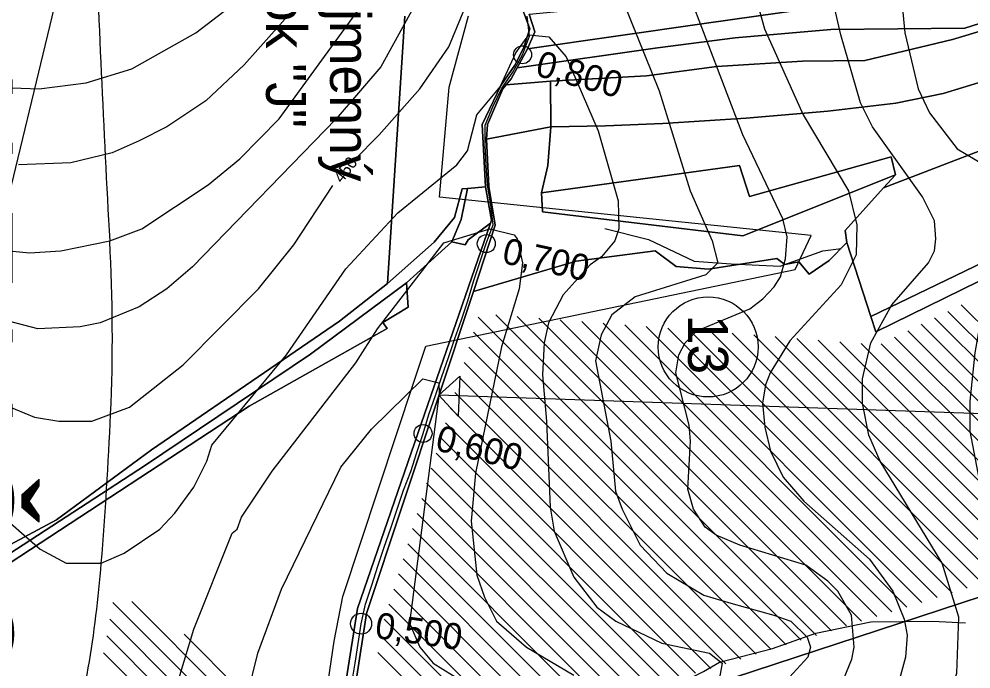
# Model space of a CAD drawing. Extents: x -510989 to -501240, y -1184665 to -1176089.
# Drawn here: x -509320.3 to -508844.5, y -1178920.9 to -1178596.2 of the extents above; entities that cross this region are included whole.
import ezdxf

# ---------------------------------------------------------------- set-up
doc = ezdxf.new("R2010")
doc.units = 0
for name, color, linetype in [('lesni_pozemek', 7, 'Continuous'), ('NAVRH_rozvodnice', 7, 'Continuous'), ('orna_puda', 7, 'Continuous'), ('ostatni_plocha_x_neplodna_puda', 7, 'Continuous'), ('ostatni_plocha_x_ostatni_komunikace', 7, 'Continuous'), ('popis', 7, 'Continuous'), ('STAV_erozne_ohrozene_plochy', 7, 'Continuous'), ('STAV_odtokove_linie', 7, 'Continuous'), ('STAV_systematicke_odvodneni', 7, 'Continuous'), ('STAV_vyrazne_udolnice', 7, 'Continuous'), ('trasovani_toku', 7, 'Continuous'), ('trvaly_travni_porost', 7, 'Continuous'), ('vodni_plocha_x_vodni_tok_v_koryt_prir_n_upr', 7, 'Continuous'), ('vrstevnice_01', 7, 'Continuous'), ('vrstevnice_02', 7, 'Continuous'), ('vrstevnice_04', 7, 'Continuous')]:
    doc.layers.add(name, color=color, linetype=linetype)

msp = doc.modelspace()

# ---------------------------------------------------------------- linework, layer by layer
at = {"layer": 'lesni_pozemek'}
for points in [[(-508694.2, -1178531.12), (-508773.17, -1178567.76), (-508848.8, -1178589.27), (-508905.8, -1178590.26), (-508927.09, -1178591.28), (-508977.94, -1178598.38), (-509066.11, -1178611.08), (-509062.51, -1178602.52), (-509065.29, -1178593.71), (-509035.54, -1178590.95), (-509002.31, -1178585.02), (-508917.7, -1178573.41), (-508856.26, -1178566.38), (-508819.35, -1178554.28), (-508781.68, -1178540.86), (-508765.23, -1178532.27), (-508699.99, -1178506.32)], [(-508691.9, -1178539.27), (-508717.79, -1178553.24), (-508749.42, -1178566.28), (-508768.45, -1178575.36), (-508847.66, -1178600.8), (-508914.58, -1178601.44), (-508962.38, -1178605.49), (-509001.19, -1178610.54), (-509071.33, -1178620.51), (-509066.11, -1178611.08), (-508977.94, -1178598.38), (-508927.09, -1178591.28), (-508905.8, -1178590.26), (-508848.8, -1178589.27), (-508773.17, -1178567.76), (-508694.2, -1178531.12)], [(-508689.7, -1178547.08), (-508768.8, -1178580.92), (-508819.34, -1178596.04), (-508853.82, -1178606.35), (-508897.56, -1178616.84), (-508928.77, -1178617.24), (-508971.61, -1178619.89), (-509006.67, -1178624.56), (-509054.7, -1178627.16), (-509076.91, -1178629.11), (-509074.36, -1178626), (-509071.33, -1178620.51), (-509001.19, -1178610.54), (-508962.38, -1178605.49), (-508914.58, -1178601.44), (-508847.66, -1178600.8), (-508768.45, -1178575.36), (-508749.42, -1178566.28), (-508717.79, -1178553.24), (-508691.9, -1178539.27)], [(-508685.06, -1178563.52), (-508683.92, -1178574.65), (-508712.94, -1178585.61), (-508741.33, -1178597.92), (-508796.54, -1178617.89), (-508838.72, -1178627.31), (-508858.45, -1178633.41), (-508882.13, -1178638.15), (-508916.08, -1178642.26), (-508956.82, -1178645.68), (-508998.59, -1178648.35), (-509027.25, -1178649.57), (-509054.58, -1178650.03), (-509054.7, -1178627.16), (-509006.67, -1178624.56), (-508971.61, -1178619.89), (-508928.77, -1178617.24), (-508897.56, -1178616.84), (-508853.82, -1178606.35), (-508819.34, -1178596.04), (-508768.8, -1178580.92), (-508689.7, -1178547.08)], [(-508712.94, -1178585.61), (-508683.92, -1178574.65), (-508680.85, -1178604.64), (-508791.99, -1178643.51), (-508888.15, -1178680.51), (-508882.24, -1178674), (-508884.37, -1178665.06), (-508955.25, -1178684.75), (-508960.15, -1178669.29), (-509059.22, -1178683.03), (-509056.08, -1178669.28), (-509054.58, -1178650.03), (-509027.25, -1178649.57), (-508998.59, -1178648.35), (-508956.82, -1178645.68), (-508916.08, -1178642.26), (-508882.13, -1178638.15), (-508858.45, -1178633.41), (-508838.72, -1178627.31), (-508796.54, -1178617.89), (-508741.33, -1178597.92)], [(-508680.85, -1178604.64), (-508669.27, -1178651.7), (-508749.47, -1178676.41), (-508794.13, -1178696.5), (-508842.69, -1178719.84), (-508894.51, -1178744.76), (-508906.64, -1178707.76), (-508907.44, -1178701.76), (-508888.15, -1178680.51), (-508791.99, -1178643.51)]]:
    msp.add_lwpolyline(points, close=True, dxfattribs=at)
at = {"layer": 'NAVRH_rozvodnice'}
for centre, radius, start, end in [((-501370.86, -1178265.59), 7916.45, 181.979217, 183.19639), ((-510129.72, -1178754.73), 856.05, 357.40438, 3.19639), ((-511480, -1178693.52), 2207.72, 355.46708, 357.40438), ((-509866.59, -1178821.43), 589.24, 345.19507, 355.46708)]:
    msp.add_arc(centre, radius, start, end, dxfattribs=at)
at = {"layer": 'orna_puda'}
for points in [[(-509070.81, -1178585.19), (-509064.96, -1178601), (-509068.2, -1178610.67), (-509072.47, -1178619.27), (-509079.57, -1178629.42), (-509088.82, -1178648.83), (-509087.14, -1178679.95), (-509096.12, -1178680.81), (-509098.79, -1178681.07), (-509102.66, -1178695.24), (-509112.8, -1178707.68), (-509136.21, -1178728.22), (-509127.44, -1178594.74)], [(-509324.76, -1178867.81), (-509205.31, -1178789.52), (-509136.23, -1178750.79), (-509138.56, -1178747.71), (-509125.79, -1178740.08), (-509126.72, -1178727.98), (-509104.07, -1178707.47), (-509097.3, -1178708.89), (-509095.81, -1178706.46), (-509084.62, -1178698.12), (-509117.59, -1178793.61), (-509151.09, -1178890.59), (-509168.68, -1179001.25), (-509186.91, -1179112.93)], [(-508838.84, -1178884.57), (-508994.39, -1178935.46), (-509162.19, -1178993.59), (-509146.65, -1178893.13), (-509093.21, -1178732.21), (-509041.89, -1178717.09), (-509002.41, -1178711.97), (-508991.88, -1178719.79), (-508975.78, -1178721.18), (-508941.58, -1178715.83), (-508937.49, -1178718.86), (-508930.53, -1178717.43), (-508925.43, -1178723.64), (-508915.45, -1178716.88), (-508906.64, -1178707.76), (-508894.51, -1178744.76), (-508892.02, -1178752.36), (-508779.86, -1178697.4)]]:
    msp.add_lwpolyline(points, dxfattribs=at)
at = {"layer": 'ostatni_plocha_x_neplodna_puda'}
for points in [[(-508667.58, -1178658.57), (-508779.86, -1178697.4), (-508892.02, -1178752.36), (-508894.51, -1178744.76), (-508842.69, -1178719.84), (-508794.13, -1178696.5), (-508749.47, -1178676.41), (-508669.27, -1178651.7)], [(-509098.79, -1178681.07), (-509096.12, -1178680.81), (-509099.38, -1178696.28), (-509104.07, -1178707.47), (-509126.72, -1178727.98), (-509174.65, -1178763.65), (-509257.53, -1178819.36), (-509328.77, -1178865.74), (-509341.07, -1178870.59), (-509343.66, -1178866.41), (-509331.92, -1178862.59), (-509301.57, -1178846.31), (-509254.05, -1178811.34), (-509160.2, -1178747.16), (-509136.21, -1178728.22), (-509112.8, -1178707.68), (-509102.66, -1178695.24)], [(-509096.12, -1178680.81), (-509087.14, -1178679.95), (-509084.09, -1178696.58), (-509084.62, -1178698.12), (-509095.81, -1178706.46), (-509097.3, -1178708.89), (-509104.07, -1178707.47), (-509099.38, -1178696.28)]]:
    msp.add_lwpolyline(points, close=True, dxfattribs=at)
at = {"layer": 'ostatni_plocha_x_ostatni_komunikace'}
msp.add_lwpolyline([(-509126.72, -1178727.98), (-509125.79, -1178740.08), (-509138.56, -1178747.71), (-509136.23, -1178750.79), (-509205.31, -1178789.52), (-509324.76, -1178867.81), (-509358.82, -1178882.2), (-509377.09, -1178891.95), (-509408.27, -1178926.19), (-509410.12, -1178922.08), (-509408.07, -1178919.73), (-509378.4, -1178889.53), (-509357.59, -1178878.19), (-509341.07, -1178870.59), (-509328.77, -1178865.74), (-509257.53, -1178819.36), (-509174.65, -1178763.65)], close=True, dxfattribs=at)
at = {"layer": 'STAV_erozne_ohrozene_plochy'}
for p, q in [((-508849.33, -1178738.98), (-508729.27, -1178859.04)), ((-509082, -1178743.9), (-508921.78, -1178904.11)), ((-508856, -1178742.21), (-508737.69, -1178860.51)), ((-509090.76, -1178745.04), (-508929.33, -1178906.47)), ((-509071.26, -1178744.74), (-508914.24, -1178901.76)), ((-509060.52, -1178745.58), (-508906.7, -1178899.4)), ((-509049.78, -1178746.42), (-508899.16, -1178897.04)), ((-509039.03, -1178747.27), (-508891.62, -1178894.68)), ((-509028.29, -1178748.11), (-508884.07, -1178892.33)), ((-508862.66, -1178745.44), (-508746.12, -1178861.99)), ((-509093.11, -1178752.59), (-508936.87, -1178908.83)), ((-509017.55, -1178748.95), (-508876.53, -1178889.97)), ((-509006.81, -1178749.79), (-508868.99, -1178887.61)), ((-508996.07, -1178750.64), (-508861.45, -1178885.25)), ((-508985.32, -1178751.48), (-508853.91, -1178882.89)), ((-508974.58, -1178752.32), (-508846.37, -1178880.54)), ((-508963.84, -1178753.16), (-508838.8, -1178878.2)), ((-508876, -1178751.91), (-508762.97, -1178864.94)), ((-508869.33, -1178748.68), (-508754.55, -1178863.46)), ((-508953.1, -1178754.01), (-508830.38, -1178876.73)), ((-508942.35, -1178754.85), (-508821.95, -1178875.25)), ((-508931.61, -1178755.69), (-508813.52, -1178873.78)), ((-508920.87, -1178756.53), (-508805.1, -1178872.31)), ((-508910.13, -1178757.38), (-508796.67, -1178870.83)), ((-508882.66, -1178755.14), (-508771.4, -1178866.41)), ((-509095.46, -1178760.14), (-508944.41, -1178911.19)), ((-508899.39, -1178758.22), (-508788.25, -1178869.36)), ((-508889.33, -1178758.38), (-508779.82, -1178867.88)), ((-509097.81, -1178767.69), (-508951.95, -1178913.54)), ((-509100.15, -1178775.24), (-508959.49, -1178915.9)), ((-509102.5, -1178782.79), (-508967.03, -1178918.26)), ((-509104.85, -1178790.34), (-508974.58, -1178920.62)), ((-509107.2, -1178797.89), (-508982.12, -1178922.98)), ((-509109.55, -1178805.44), (-508989.66, -1178925.33)), ((-509111.9, -1178812.99), (-508997.2, -1178927.69)), ((-509114.25, -1178820.54), (-509004.74, -1178930.05)), ((-509116.6, -1178828.09), (-509012.29, -1178932.41)), ((-509118.95, -1178835.64), (-509019.83, -1178934.76)), ((-509121.3, -1178843.19), (-509027.37, -1178937.12)), ((-509123.65, -1178850.74), (-509034.91, -1178939.48)), ((-509126, -1178858.29), (-509042.45, -1178941.84)), ((-509128.35, -1178865.84), (-509049.99, -1178944.19)), ((-509130.7, -1178873.39), (-509057.54, -1178946.55)), ((-509133.05, -1178880.94), (-509065.08, -1178948.91)), ((-509273.47, -1178887.61), (-509181.48, -1178979.6)), ((-509263.94, -1178887.24), (-509180.33, -1178970.85)), ((-509135.4, -1178888.49), (-509072.62, -1178951.27)), ((-509274.99, -1178895.99), (-509182.63, -1178988.34)), ((-509137.75, -1178896.04), (-509080.16, -1178953.62)), ((-509276.5, -1178904.38), (-509183.79, -1178997.09)), ((-509237.79, -1178903.49), (-509179.17, -1178962.11)), ((-509139.58, -1178904.11), (-509087.7, -1178955.98)), ((-509278.02, -1178912.76), (-509184.94, -1179005.84)), ((-509140.97, -1178912.62), (-509095.25, -1178958.34))]:
    msp.add_line(p, q, dxfattribs=at)
at = {"layer": 'STAV_odtokove_linie'}
msp.add_line((-508745.75, -1178796.5), (-509110.46, -1178784.16), dxfattribs=at)
msp.add_lwpolyline([(-509100.87, -1178794.55), (-509110.46, -1178784.16), (-509100.07, -1178774.57)], close=True, dxfattribs=at)
msp.add_circle((-508975.86, -1178759.99), 25, dxfattribs=at)
at = {"layer": 'STAV_systematicke_odvodneni'}
for p, q in [((-509274.88, -1178474.44), (-509350.42, -1178787.38)), ((-509105.31, -1178630.27), (-509095.74, -1178594.61)), ((-509110.1, -1178685.09), (-509105.31, -1178630.27)), ((-508924.44, -1178704.25), (-509110.1, -1178685.09)), ((-508932.42, -1178721.28), (-508924.44, -1178704.25)), ((-509117.02, -1178759.6), (-508932.42, -1178721.28)), ((-509122.87, -1178777.16), (-509117.02, -1178759.6)), ((-509158.51, -1178884.67), (-509122.87, -1178777.16)), ((-509162.77, -1178907.02), (-509158.51, -1178884.67)), ((-509169.55, -1178951.83), (-509162.77, -1178907.02))]:
    msp.add_line(p, q, dxfattribs=at)
at = {"layer": 'STAV_vyrazne_udolnice'}
for points in [[(-509027.47, -1178700.74), (-509005.77, -1178706.36), (-508982.86, -1178717.21), (-508964.37, -1178718.41), (-508939.86, -1178719.62), (-508918.56, -1178711.98), (-508909.31, -1178710.78)], [(-509120.31, -1178976.33), (-509071.08, -1178958.75), (-509002.15, -1178934.15), (-508978.24, -1178922.2), (-508970.2, -1178917.47), (-508943.67, -1178910.65), (-508921.97, -1178903.01), (-508894.64, -1178897.39), (-508863.69, -1178896.99), (-508847.22, -1178897.79)]]:
    msp.add_lwpolyline(points, dxfattribs=at)
at = {"layer": 'trasovani_toku'}
for p, q in [((-509065.14, -1178604.66), (-509066.33, -1178594.73)), ((-509068.66, -1178614.02), (-509065.14, -1178604.66)), ((-509073.5, -1178622.77), (-509068.66, -1178614.02)), ((-509079.23, -1178630.97), (-509073.5, -1178622.77)), ((-509083.54, -1178639.99), (-509079.23, -1178630.97)), ((-509087.38, -1178649.22), (-509083.54, -1178639.99)), ((-509087.3, -1178659.22), (-509087.38, -1178649.22)), ((-509086.76, -1178669.21), (-509087.3, -1178659.22)), ((-509086.14, -1178679.19), (-509086.76, -1178669.21)), ((-509084.5, -1178689.05), (-509086.14, -1178679.19)), ((-509083.33, -1178698.98), (-509084.5, -1178689.05)), ((-509086.75, -1178708.38), (-509083.33, -1178698.98)), ((-509089.96, -1178717.85), (-509086.75, -1178708.38)), ((-509093.08, -1178727.35), (-509089.96, -1178717.85)), ((-509095.96, -1178736.93), (-509093.08, -1178727.35)), ((-509099.09, -1178746.43), (-509095.96, -1178736.93)), ((-509102.49, -1178755.83), (-509099.09, -1178746.43)), ((-509105.71, -1178765.3), (-509102.49, -1178755.83)), ((-509108.94, -1178774.76), (-509105.71, -1178765.3)), ((-509112.08, -1178784.26), (-509108.94, -1178774.76)), ((-509115.44, -1178793.67), (-509112.08, -1178784.26)), ((-509118.39, -1178803.23), (-509115.44, -1178793.67)), ((-509121.47, -1178812.74), (-509118.39, -1178803.23)), ((-509124.56, -1178822.25), (-509121.47, -1178812.74)), ((-509128.22, -1178831.56), (-509124.56, -1178822.25)), ((-509131.31, -1178841.07), (-509128.22, -1178831.56)), ((-509134.44, -1178850.57), (-509131.31, -1178841.07)), ((-509137.83, -1178859.97), (-509134.44, -1178850.57)), ((-509140.9, -1178869.49), (-509137.83, -1178859.97)), ((-509144.03, -1178878.99), (-509140.9, -1178869.49)), ((-509147.07, -1178888.52), (-509144.03, -1178878.99)), ((-509149.31, -1178898.26), (-509147.07, -1178888.52)), ((-509150.79, -1178908.15), (-509149.31, -1178898.26)), ((-509152.35, -1178918.03), (-509150.79, -1178908.15)), ((-509153.89, -1178927.91), (-509152.35, -1178918.03))]:
    msp.add_line(p, q, dxfattribs=at)
for centre, radius in [((-509068.66, -1178614.02), 4.5), ((-509086.75, -1178708.38), 4.5), ((-509118.39, -1178803.23), 4.5), ((-509149.31, -1178898.26), 5.25)]:
    msp.add_circle(centre, radius, dxfattribs=at)
at = {"layer": 'trvaly_travni_porost'}
msp.add_lwpolyline([(-509127.44, -1178594.74), (-509136.21, -1178728.22), (-509160.2, -1178747.16), (-509254.05, -1178811.34), (-509301.57, -1178846.31), (-509331.92, -1178862.59)], dxfattribs=at)
for points in [[(-509054.7, -1178627.16), (-509054.58, -1178650.03), (-509086.62, -1178656.21), (-509086.14, -1178648.85), (-509078.48, -1178631.01), (-509076.91, -1178629.11)], [(-509086.62, -1178656.21), (-509054.58, -1178650.03), (-509056.08, -1178669.28), (-509059.22, -1178683.03), (-509058.69, -1178692.51), (-508958.61, -1178704.53), (-508882.24, -1178674), (-508888.15, -1178680.51), (-508907.44, -1178701.76), (-508906.64, -1178707.76), (-508915.45, -1178716.88), (-508925.43, -1178723.64), (-508930.53, -1178717.43), (-508937.49, -1178718.86), (-508941.58, -1178715.83), (-508975.78, -1178721.18), (-508991.88, -1178719.79), (-509002.41, -1178711.97), (-509041.89, -1178717.09), (-509093.21, -1178732.21), (-509082.25, -1178699.18), (-509085.42, -1178679.89)], [(-508882.24, -1178674), (-508958.61, -1178704.53), (-509058.69, -1178692.51), (-509059.22, -1178683.03), (-508960.15, -1178669.29), (-508955.25, -1178684.75), (-508884.37, -1178665.06)], [(-508838.84, -1178884.57), (-508818.38, -1178938.24), (-508862.04, -1178954.97), (-508864.4, -1178955.87), (-508911.92, -1178973.72), (-508920.06, -1178991.6), (-508958.12, -1179018.3), (-508951.95, -1179029.63), (-508984.27, -1179048.63), (-509018.45, -1179069.35), (-509064.66, -1179094.07), (-509127.72, -1179124.5), (-509191.54, -1179153.27), (-509193.35, -1179148.61), (-509150.2, -1179127.94), (-509147.69, -1179120.28), (-509165.09, -1179126.1), (-509165.77, -1179124.41), (-509171.25, -1179110.67), (-509177.78, -1179094.3), (-509162.19, -1178993.59), (-508994.39, -1178935.46)]]:
    msp.add_lwpolyline(points, close=True, dxfattribs=at)
at = {"layer": 'vodni_plocha_x_vodni_tok_v_koryt_prir_n_upr'}
for points in [[(-509186.91, -1179112.93), (-509168.68, -1179001.25), (-509151.09, -1178890.59), (-509117.59, -1178793.61), (-509084.62, -1178698.12), (-509084.09, -1178696.58), (-509087.14, -1178679.95), (-509088.82, -1178648.83), (-509079.57, -1178629.42), (-509072.47, -1178619.27), (-509068.2, -1178610.67), (-509064.96, -1178601), (-509070.81, -1178585.19)], [(-509065.29, -1178593.71), (-509062.51, -1178602.52), (-509066.11, -1178611.08), (-509071.33, -1178620.51), (-509074.36, -1178626), (-509076.91, -1178629.11), (-509078.48, -1178631.01), (-509086.14, -1178648.85), (-509086.62, -1178656.21), (-509085.42, -1178679.89), (-509082.25, -1178699.18), (-509093.21, -1178732.21), (-509146.65, -1178893.13), (-509162.19, -1178993.59), (-509177.78, -1179094.3)]]:
    msp.add_lwpolyline(points, dxfattribs=at)
at = {"layer": 'vrstevnice_01'}
for points in [[(-508882.69, -1178550), (-508877.5, -1178603), (-508870.91, -1178631), (-508865.31, -1178643), (-508851.41, -1178661), (-508837.91, -1178669), (-508825.91, -1178680), (-508823.09, -1178685), (-508823.31, -1178697), (-508839.31, -1178744), (-508842.59, -1178763), (-508845, -1178787), (-508845, -1178802), (-508839.69, -1178830), (-508828.5, -1178876), (-508825.19, -1178913), (-508825.41, -1178925), (-508827.81, -1178940), (-508837, -1178974), (-508844.91, -1179046), (-508843.91, -1179057), (-508840, -1179067), (-508834, -1179076), (-508813.41, -1179095)], [(-508960.59, -1178555), (-508947.69, -1178601), (-508928.31, -1178644), (-508905.69, -1178682), (-508901.5, -1178699), (-508901.91, -1178714), (-508909.31, -1178729), (-508935, -1178757), (-508944.91, -1178773), (-508947.19, -1178779), (-508948.69, -1178788), (-508947.59, -1178800), (-508944.69, -1178812), (-508938.31, -1178825), (-508928.09, -1178837), (-508895.19, -1178866), (-508883.5, -1178882), (-508877.91, -1178896), (-508876.41, -1178904), (-508877.31, -1178915), (-508880.19, -1178926)], [(-509345.31, -1178710), (-509315, -1178713), (-509299.41, -1178712), (-509275, -1178707), (-509259, -1178701), (-509225.81, -1178679), (-509210, -1178666), (-509190.31, -1178646), (-509143.19, -1178581)], [(-509337.5, -1178630), (-509310.31, -1178631), (-509286.81, -1178628), (-509263.91, -1178621), (-509232, -1178603), (-509202.19, -1178580)], [(-509152.77, -1178666.68), (-509140.31, -1178654), (-509120, -1178631), (-509105.5, -1178610), (-509092.31, -1178578)], [(-509021.69, -1178579), (-509000.31, -1178632), (-508984.91, -1178682), (-508973.81, -1178707), (-508971.09, -1178718), (-508977.09, -1178724), (-509012.31, -1178735), (-509024, -1178744), (-509029.41, -1178754), (-509032.19, -1178767), (-509024.59, -1178807), (-509022.19, -1178832), (-509018.81, -1178841), (-509009.81, -1178859), (-508996.5, -1178873), (-508978, -1178884), (-508964.5, -1178888), (-508943.09, -1178894), (-508934.5, -1178897), (-508926.31, -1178905), (-508924.69, -1178910), (-508926.09, -1178915), (-508940.69, -1178931)], [(-509341.81, -1178783), (-509312.59, -1178795), (-509300.5, -1178797), (-509284, -1178797), (-509265.09, -1178790), (-509238.31, -1178769), (-509200.59, -1178731), (-509182.91, -1178709), (-509163.43, -1178679.28)], [(-509242.69, -1178933), (-509232.91, -1178901), (-509213.81, -1178853), (-509211.31, -1178851), (-509209.09, -1178845), (-509193.81, -1178822), (-509151.91, -1178768), (-509141.09, -1178751), (-509108, -1178708), (-509085, -1178701), (-509072.81, -1178704), (-509071.31, -1178706), (-509068.59, -1178718), (-509070.41, -1178731), (-509079.09, -1178760), (-509092.09, -1178823), (-509094.31, -1178847), (-509091.5, -1178874), (-509087.69, -1178885), (-509081.69, -1178897), (-509066.69, -1178910), (-509043, -1178924)]]:
    msp.add_lwpolyline(points, dxfattribs=at)
at = {"layer": 'vrstevnice_02'}
for points in [[(-508922.91, -1178962), (-508904, -1178916), (-508902.81, -1178910), (-508904.19, -1178894), (-508911, -1178882), (-508916.09, -1178877), (-508927, -1178869), (-508960.09, -1178859), (-508971.81, -1178854), (-508977.31, -1178850), (-508983.19, -1178841), (-508986, -1178831), (-508984.69, -1178807), (-508985.41, -1178799), (-508992.09, -1178773), (-508990.59, -1178764), (-508987.31, -1178758), (-508981.59, -1178752), (-508955, -1178741), (-508948.5, -1178736), (-508942.91, -1178730), (-508939.69, -1178725), (-508937.19, -1178716), (-508936.31, -1178705), (-508938.5, -1178696), (-508958.5, -1178654), (-508995.19, -1178558)], [(-509118.59, -1178582), (-509139.5, -1178620), (-509161.81, -1178646), (-509233.69, -1178720), (-509246.5, -1178731), (-509260.31, -1178740), (-509279.69, -1178748), (-509289.69, -1178750), (-509311, -1178751), (-509349.19, -1178741)], [(-508884.91, -1179088), (-508882.31, -1179063), (-508872.31, -1179032), (-508867.41, -1178981), (-508864.59, -1178964), (-508851.59, -1178923), (-508850.5, -1178895), (-508858.91, -1178868), (-508889.91, -1178817), (-508895.5, -1178804), (-508898.69, -1178788), (-508898.69, -1178776), (-508894.5, -1178758), (-508884.09, -1178739), (-508865.81, -1178718), (-508862.81, -1178712), (-508862.09, -1178706), (-508862.81, -1178697), (-508868.69, -1178685), (-508893.81, -1178650), (-508899.81, -1178638), (-508909.59, -1178604), (-508915.09, -1178580)], [(-509187.31, -1178596), (-509207.81, -1178619), (-509226.91, -1178637), (-509246.5, -1178650), (-509260.31, -1178657), (-509273.81, -1178663), (-509294.41, -1178668), (-509320.59, -1178669)], [(-509332.69, -1178841), (-509309.69, -1178861), (-509296.69, -1178868), (-509285.59, -1178868), (-509279.19, -1178868), (-509267.69, -1178863), (-509249.91, -1178851), (-509242.5, -1178843), (-509233, -1178830), (-509226.5, -1178817), (-509223.91, -1178809), (-509186.69, -1178764), (-509156.91, -1178721), (-509130.91, -1178693), (-509101.41, -1178669), (-509096.09, -1178662), (-509091.5, -1178644), (-509079.91, -1178630), (-509072, -1178613), (-509065.5, -1178604), (-509055.5, -1178605), (-509046.91, -1178615), (-509030.91, -1178652), (-509020.91, -1178687), (-509020.5, -1178701), (-509022.5, -1178707), (-509029.19, -1178715), (-509034.91, -1178719), (-509048.31, -1178734), (-509055.59, -1178748), (-509057.91, -1178758), (-509058.59, -1178774), (-509056.69, -1178797), (-509054.91, -1178840), (-509052.91, -1178852), (-509043.09, -1178875), (-509031.59, -1178890), (-509022.09, -1178897), (-508999.09, -1178908), (-508975.19, -1178913), (-508968.91, -1178918), (-508970.81, -1178929)], [(-509206.19, -1178934), (-509201, -1178913), (-509189.19, -1178881), (-509159.5, -1178820), (-509144.19, -1178801), (-509118.5, -1178776), (-509110.5, -1178778), (-509110.31, -1178783), (-509125.09, -1178898), (-509120, -1178910), (-509113.31, -1178918), (-509098.81, -1178927)]]:
    msp.add_lwpolyline(points, dxfattribs=at)

# ---------------------------------------------------------------- texts
at = {"layer": 'NAVRH_rozvodnice'}
for s, p in [('Bezejmenný', (-509164.86, -1178530.18)), ('přítok "J"', (-509196.86, -1178543.9))]:
    msp.add_text(s, height=20, rotation=270, dxfattribs=at).set_placement(p)
at = {"layer": 'popis'}
msp.add_text('N E V Š O V Á', height=50, rotation=270, dxfattribs=at).set_placement((-509373.44, -1178620.73))
at = {"layer": 'STAV_odtokove_linie'}
msp.add_text('13', height=20, rotation=270, dxfattribs=at).set_placement((-508985.88, -1178743.88))
at = {"layer": 'trasovani_toku'}
for s, rotation, p in [('0,800', 344.6322, (-509062.82, -1178624.23)), ('0,700', 347.6755, (-509079.44, -1178717.98)), ('0,600', 346.0071, (-509112.83, -1178811.43)), ('0,500', 351.7838, (-509142.87, -1178905.31))]:
    msp.add_text(s, height=13, rotation=rotation, dxfattribs=at).set_placement(p)
at = {"layer": 'vrstevnice_04'}
msp.add_text('450', height=6, rotation=52.5441, dxfattribs=at).set_placement((-509158.91, -1178678.53))

doc.saveas('drawing.dxf')
